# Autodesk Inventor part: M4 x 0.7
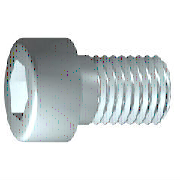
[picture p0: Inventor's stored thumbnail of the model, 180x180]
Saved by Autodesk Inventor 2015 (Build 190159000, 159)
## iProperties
IsCustomPart: 0
Created: 2015-10
Part Number: M4 x 0.7
Material: Steel, Mild
Description: 6각머리 태핑 나사
Document SubType Name: Modeling
Standard: KS B 1003
Designer: mdu
Standards Organization: KS
Language: ko-KR
Size Designation: M 4 x 25
Categories: <MemberInstance><Categories><Category DisplayName="조임쇠" InternalName="e4da775c-781d-43d5-af7c-5136215cf5a6" Mnemonic="FSTN"><Category DisplayName="볼트" InternalN
Density: 1 g/cm^3
Appearance: Steel
Author: mdu
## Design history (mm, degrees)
revolve "본체" stored, may be unused: angle "d10" = 90 deg
sketch "스케치2"
  geometry: L1 (0, -4.9)-(0, 4.9) reference; L2 (-4.9, 0)-(4.9, 0) reference; L3 (1.732, 0)-(0.866, -1.5); L4 (0.866, -1.5)-(-0.866, -1.5); L5 (-0.866, -1.5)-(-1.732, 0); L6 (-1.732, 0)-(-0.866, 1.5); L7 (-0.866, 1.5)-(0.866, 1.5); L8 (0.866, 1.5)-(1.732, 0); 2 further points
  constraints: 12 end point, 1 coincident, 1 horizontal alignment, 1 point on line, 12 other
extrude "슬롯" join sketch "스케치2" stored distance "d11" = 10; taper "d12" = 0 deg
workplane "Work Plane1"
fillet "Fillet2" dims "d30" = 0.1 (= R)
body "Solid1"
fillet "모깎기1" dims "d17" = 0.4 (= RR)
feature "스레드" dims "d13" = 23.25 (= GEL), "d14" = 0
chamfer "모따기1" distance "d15" = 0.42941 (= -0.5 x SPD + 0.5 x GD); stored, may be unused: second distance "d16" = 0.42941 (= GUL), angle "d27" = 45 deg
sketch "스케치1"
  geometry: L1 (-1, 0)-(25, 0); L2 (25, 0)-(25, 2); L3 (25, 2)-(1.75, 2); L4 (1.75, 2)-(1.32, 2); L5 (1.32, 2)-(0, 2); L6 (0, 2)-(0, 3.5); L7 (0, 3.5)-(-4, 3.5); L8 (-4, 3.5)-(-4, 1.732); L9 (-4, 1.732)-(-2, 1.732); L10 (-2, 1.732)-(-1, 0); L11 (-9.8, 0)-(30.8, 0) reference; L12 (0, -0.7)-(0, 4.2) reference; L13 (1.75, 2)-(0, 2)
  constraints: 22 end point, 6 parallel, 2 collinear, 2 perpendicular, 1 horizontal, 1 point on line
  dimensions: "d1" = 23.25 distance from line of L3.end L2 (= GEL); "d2" = 0.42952 distance of L4.end L3.end (computed from GAL); "d3" = 4 distance between parallel lines of L8 L6 (= KOH); "d4" = 2 distance of L8.end L9.end (= INTI); "d5" = 60 deg angle of L10 L1; "d6" = 4 diameter of L3 L1 (= GD); "d7" = 4 diameter of L5 L1 (= BDM); "d8" = 3.4641 diameter of L9 L1 (= 1.1547 x SW); "d9" = 7 diameter of L7 L1 (= KOD); "d26" = 25 distance between parallel lines of L12 L2 (= NLG)
other parameters: "GD" = 4 (= NND) [user parameter; used in 2 equation terms], "NLG" = 25 [user parameter; used in 1 equation term], "GEL" = 23.25 [user parameter; used in 2 equation terms], "KOD" = 7 [user parameter; used in 1 equation term], "KOH" = 4 [user parameter; used in 1 equation term], "INTI" = 2 [user parameter; used in 1 equation term], "GAL" = 0.42941 (= 0.61345 x PTC) [user parameter; used in 1 equation term], "GUL" = 0.42941 (= 0.61345 x PTC) [user parameter; used in 1 equation term], "BDM" = 4 (= NND) [user parameter; used in 1 equation term], "SW" = 3 [user parameter; used in 2 equation terms], "RR" = 0.4 [user parameter; used in 1 equation term], "SPD" = 3.14117 (= NND - 1.2269 x PTC) [user parameter; used in 1 equation term], "d19" = 0, "d28" = 0, "d29" = 0, "R" = 0.1 [user parameter; used in 1 equation term], "PHH" = 0.2 [user parameter], "GD1" = 3.14117 (= THREADDIA - 1.2269 x PTC) [user parameter], "THREADDIA" = 4 [user parameter; used in 1 equation term], "FAWI" = 45 deg [user parameter], "TPU" = 14.28571 (computed from PTC) [user parameter], "PTC" = 0.7 [user parameter; used in 5 equation terms], "NND" = 4 [user parameter; used in 3 equation terms], "TOA" = 30 deg [user parameter], "E0" = 3.465 (= 1.155 x SW) [user parameter]
